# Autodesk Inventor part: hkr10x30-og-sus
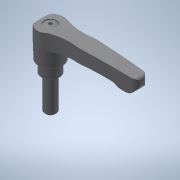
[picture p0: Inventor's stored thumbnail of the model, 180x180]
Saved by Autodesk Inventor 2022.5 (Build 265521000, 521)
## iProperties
Created: 2017-09
Part Number: hkr10x30-og-sus
Material: 一般
Document SubType Name: Modeling
Designer: imaocorp
Density: 1 g/cm^3
Appearance: 既定
Author: imaocorp
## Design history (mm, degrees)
node "hkr10x30-og-sus.x_t1"
node "hkr10x30-og-sus"
node "Base1"
